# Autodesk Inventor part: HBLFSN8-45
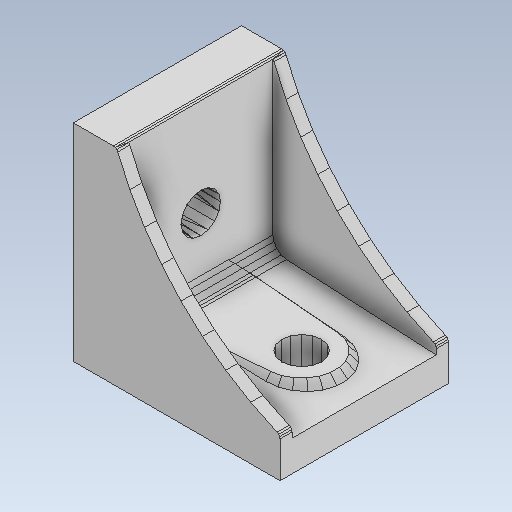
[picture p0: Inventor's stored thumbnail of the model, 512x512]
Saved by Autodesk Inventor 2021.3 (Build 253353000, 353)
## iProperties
Created: 2022-02
Part Number: HBLFSN8-45
Material: 一般
Document SubType Name: Modeling
Designer: kengo
Density: 1 g/cm^3
Appearance: 既定
Author: kengo
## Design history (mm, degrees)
feature "HBLFSN8-45"
node "ソリッド1"
